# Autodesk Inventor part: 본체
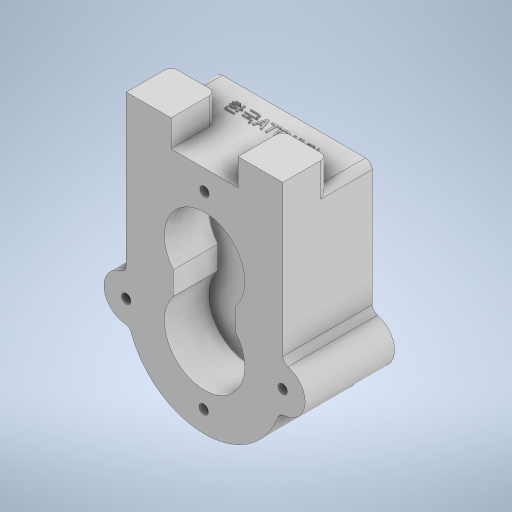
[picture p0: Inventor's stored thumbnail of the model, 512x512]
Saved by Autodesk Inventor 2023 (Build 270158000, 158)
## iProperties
Created: 2024-03
Part Number: 본체
Material: 일반
Document SubType Name: Modeling
Designer: asung
Density: 1 g/cm^3
Appearance: 기본값
Author: asung
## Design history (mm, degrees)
sketch "스케치1"
  geometry: L1 (-35, 0)-(35, 0); L2 (35, 0)-(35, 68); L3 (35, 68)-(-35, 68); L4 (-35, 68)-(-35, 0); C1 r 10 at (-35, 0); C2 r 10 at (35, 0); A1 r 35 centre (0, 0) between (-35, 0) and (35, 0); 7 further points
  constraints: 8 end point, 3 centre point, 2 horizontal alignment, 2 midpoint, 2 parallel, 2 point on circle, 1 coincident, 1 horizontal, 1 perpendicular, 1 vertical alignment
  dimensions: "d1" = 70 diameter of A1; "d4" = 10 radius of C1; "d5" = 10 radius of C2; "d6" = 70 distance of L3.end L2.end; "d7" = 68 distance of L2.end L1.end
extrude "돌출1" new body sketch "스케치1" distance "d8" = 40; taper "d9" = 0 deg
sketch "스케치2"
  geometry: L1 (0, 0)-(0, 33); L2 (-14, 0)-(0, 0); L3 (14, 11.314)-(14, 21.686); L4 (-14, 21.686)-(-14, 11.314); A1 r 18 centre (0, 33) between (14, 21.686) and (-14, 21.686); A2 r 18 centre (0, 0) between (-14, 11.314) and (14, 11.314); 1 further point
  constraints: 8 end point, 4 point on circle, 2 centre point, 2 coincident, 2 vertical, 1 horizontal
  dimensions: "d11" = 33 distance of L1.start L1.end
extrude "돌출2" cut sketch "스케치2" distance "d19" = 20; taper "d20" = 0 deg
sketch "스케치3"
  geometry: A1 r 18 centre (0, 33) between (14, 21.686) and (-14, 21.686) reference; 2 further points
  constraints: 1 coincident
hole "구멍1" sketch "스케치3" at (0, 33) diameter "d21" = 15; stored, may be unused: countersink angle "d25" = 90 deg, drill point angle "d27" = 0 deg; dims "d22" = 8, "d23" = 20, "d24" = 10, "d26" = 30
sketch "스케치5"
  geometry: L1 (35, 68)-(35, 10) reference; L2 (-35, 68)-(35, 68) reference; L3 (-35, 10)-(-35, 68) reference; C1 r 7.5 at (0, 33) reference; C2 r 7.5 at (0, 33) reference; C3 r 26 at (0, 33); A1 r 10 centre (-35, 0) between (-35, 10) and (-33.571, -9.897) reference; A2 r 35 centre (0, 0) between (-33.571, -9.897) and (33.571, -9.897) reference; A3 r 10 centre (35, 0) between (33.571, -9.897) and (35, 10) reference; 1 further point
  constraints: 1 centre point, 1 coincident
  dimensions: "d35" = 52 diameter of C3
extrude "돌출3" join sketch "스케치5" distance "d36" = 6; taper "d37" = 0 deg
sketch "스케치6" dims "d38" = 42
  geometry: 3 further points
  constraints: 1 horizontal alignment, 2 other
hole "구멍3" sketch "스케치6" at (21, 0) diameter "d39" = 3.242; stored, may be unused: countersink angle "d43" = 90 deg, drill point angle "d45" = 118 deg; dims "d40" = 8, "d41" = 25, "d42" = 7.3, "d44" = 10
sketch "스케치7" dims "d8" = 40
  geometry: C1 r 26 at (0, 0) reference; 2 further points
  constraints: 1 coincident
hole "구멍4" sketch "스케치7" at (0, 0) diameter "d49" = 15; stored, may be unused: countersink angle "d53" = 90 deg, drill point angle "d55" = 0 deg; dims "d8" = 40, "d50" = 8, "d51" = 25, "d52" = 7.3, "d54" = 50
fillet "모깎기1" dims "d56" = 3
chamfer "모따기1" distance "d57" = 1; stored, may be unused: second distance "d58" = 2, angle "d59" = 45 deg
sketch "스케치8"
  geometry: L1 (35, 68)-(35, 10) reference; L2 (-35, 68)-(35, 68) reference; L3 (-35, 10)-(-35, 68) reference; C1 r 29 at (0, 33) reference; A1 r 10 centre (-35, 0) between (-35, 10) and (-33.571, -9.897) reference; A2 r 35 centre (0, 0) between (-33.571, -9.897) and (33.571, -9.897) reference; A3 r 10 centre (35, 0) between (33.571, -9.897) and (35, 10) reference; 1 further point
  node "투영된 루프2"
sketch "스케치11"
  geometry: A1 r 10 centre (-35, 0) between (-35, 10) and (-33.571, -9.897) reference; 2 further points
  constraints: 1 coincident
hole "구멍6" sketch "스케치11" at (-35, 0) diameter "d69" = 4.134; stored, may be unused: countersink angle "d73" = 90 deg, drill point angle "d75" = 120 deg; dims "d70" = 10, "d71" = 4, "d72" = 2, "d74" = 12
sketch "스케치12"
  geometry: A1 r 10 centre (35, 0) between (33.571, -9.897) and (35, 10) reference; 2 further points
  constraints: 1 coincident
hole "구멍7" sketch "스케치12" at (35, 0) diameter "d76" = 4.134; stored, may be unused: countersink angle "d80" = 90 deg, drill point angle "d82" = 120 deg; dims "d77" = 10, "d78" = 4, "d79" = 2, "d81" = 12
sketch "스케치13"
  geometry: 2 further points
hole "구멍8" sketch "스케치13" at (1.299, -1.231) diameter "d83" = 10; stored, may be unused: countersink angle "d87" = 90 deg, drill point angle "d89" = 120 deg; dims "d84" = 10, "d85" = 4, "d86" = 2, "d88" = 12
sketch "스케치14"
  geometry: C1 r 2.067 at (-35, 0) reference; C2 r 10 at (-35, 0); C3 r 2.067 at (35, 0) reference; C4 r 10 at (35, 0); 1 further point
  constraints: 2 centre point, 2 coincident
  dimensions: "d90" = 20 diameter of C2; "d91" = 20 diameter of C4
sketch "스케치15"
  geometry: 1 further point
node "작업 평면3"
sketch "스케치16"
  geometry: L1 (0, -20)-(20, -20); L2 (20, -20)-(20, -40); L3 (20, -40)-(0, -40); L4 (0, -40)-(0, -20); L5 (50, -20)-(70, -20); L6 (70, -20)-(70, -40); L7 (70, -40)-(50, -40); L8 (50, -40)-(50, -20); L9 (70, 0)-(0, 0) reference; L10 (0, 0)-(0, -40) reference; L11 (70, -40)-(0, -40) reference; L12 (70, 0)-(70, -40) reference; 1 further point
  constraints: 16 end point, 4 parallel, 2 horizontal, 2 perpendicular, 2 point on line
  dimensions: "d93" = 20 distance of L3.end L2.end; "d94" = 20 distance of L6.end L7.end; "d95" = 30 distance of L7.end L2.end; "d96" = 20 distance of L2.end L1.end
extrude "돌출4" join sketch "스케치16" stored distance "d97" = 12; taper "d98" = 0 deg
fillet "모깎기2" dims "d99" = 3
sketch "스케치17"
  geometry: L1 (17, -20)-(3, -20) reference; L2 (0, -23)-(0, -40) reference; L3 (0, -40)-(20, -40) reference; L4 (20, -40)-(20, -23) reference; L5 (67, -20)-(53, -20) reference; L6 (50, -23)-(50, -40) reference; L7 (50, -40)-(70, -40) reference; L8 (70, -40)-(70, -23) reference; A1 r 3 centre (17, -23) between (20, -23) and (17, -20) reference; A2 r 3 centre (3, -23) between (3, -20) and (0, -23) reference; A3 r 3 centre (67, -23) between (70, -23) and (67, -20) reference; A4 r 3 centre (53, -23) between (53, -20) and (50, -23) reference; 1 further point
  node "투영된 루프4"
  node "투영된 루프5"
sketch "스케치18"
  geometry: 1 further point
sketch "스케치19"
  geometry: L1 (30, 0)-(0, 0) reference; L2 (47, 40)-(-17, 40) reference; 3 further points
  constraints: 1 midpoint, 1 vertical alignment, 1 other
  dimensions: "d100" = 30 distance from line of L1 point (15, 30)
feature "엠보싱1" sketch "스케치19" dims "d101" = 0.5, "d102" = 0
sketch "스케치20"
  geometry: L1 (35, 10)-(35, 80) reference; L2 (15, 80)-(35, 80) reference; L3 (15, 80)-(15, 68) reference; L4 (15, 68)-(-15, 68) reference; L5 (-15, 80)-(-15, 68) reference; L6 (-35, 80)-(-15, 80) reference; L7 (-35, 80)-(-35, 10) reference; L8 (-14, 11.314)-(-14, 21.686) reference; L9 (14, 21.686)-(14, 11.314) reference; L10 (0, 33)-(0, 59); C1 r 2.067 at (35, 0) reference; C2 r 2.067 at (-35, 0) reference; C3 r 10 at (0, 33) reference; A1 r 10 centre (-35, 0) between (-35, 10) and (-33.571, -9.897) reference; A2 r 35 centre (0, 0) between (-33.571, -9.897) and (33.571, -9.897) reference; A3 r 10 centre (35, 0) between (33.571, -9.897) and (35, 10) reference; A4 r 18 centre (0, 0) between (-14, 11.314) and (14, 11.314) reference; A5 r 18 centre (0, 33) between (14, 21.686) and (-14, 21.686) reference; 2 further points
  constraints: 2 end point, 1 coincident, 1 vertical
  dimensions: "d103" = 26 distance of L10.start L10.end
hole "구멍9" sketch "스케치20" at (0, 59) diameter "d104" = 4.134; stored, may be unused: countersink angle "d108" = 90 deg, drill point angle "d110" = 120 deg; dims "d105" = 10, "d106" = 4, "d107" = 2, "d109" = 12
sketch "스케치21"
  geometry: L1 (-0.336, 68)-(-0.336, 68.5) reference; L2 (-0.336, 68.5)-(-0.336, -25.5); 2 further points
  constraints: 2 end point, 1 coincident, 1 vertical
  dimensions: "d111" = 94 distance of L1.end L2.end
hole "구멍10" sketch "스케치21" at (-0.336, -25.5) diameter "d112" = 4.134; stored, may be unused: countersink angle "d116" = 90 deg, drill point angle "d118" = 120 deg; dims "d113" = 10, "d114" = 4, "d115" = 2, "d117" = 12
fillet "모깎기3" dims "d119" = 3
sketch "스케치22"
  geometry: 1 further point
node "솔리드1"
pattern_circular "원형 패턴1" dims angle "d47" = 360 deg
node "투영된 루프1"
node "투영된 루프3"
node "투영된 루프6"
feature "A9D066F2-1C7D-4E18-AEED-F7BC21143FA4" dims "d21" = 15, "d22" = 8, "d23" = 20, "d24" = 10, "d25" = 90 deg, "d26" = 30, "d27" = 0
other parameters: "d10" = 36, "d12" = 36, "d92" = 12
